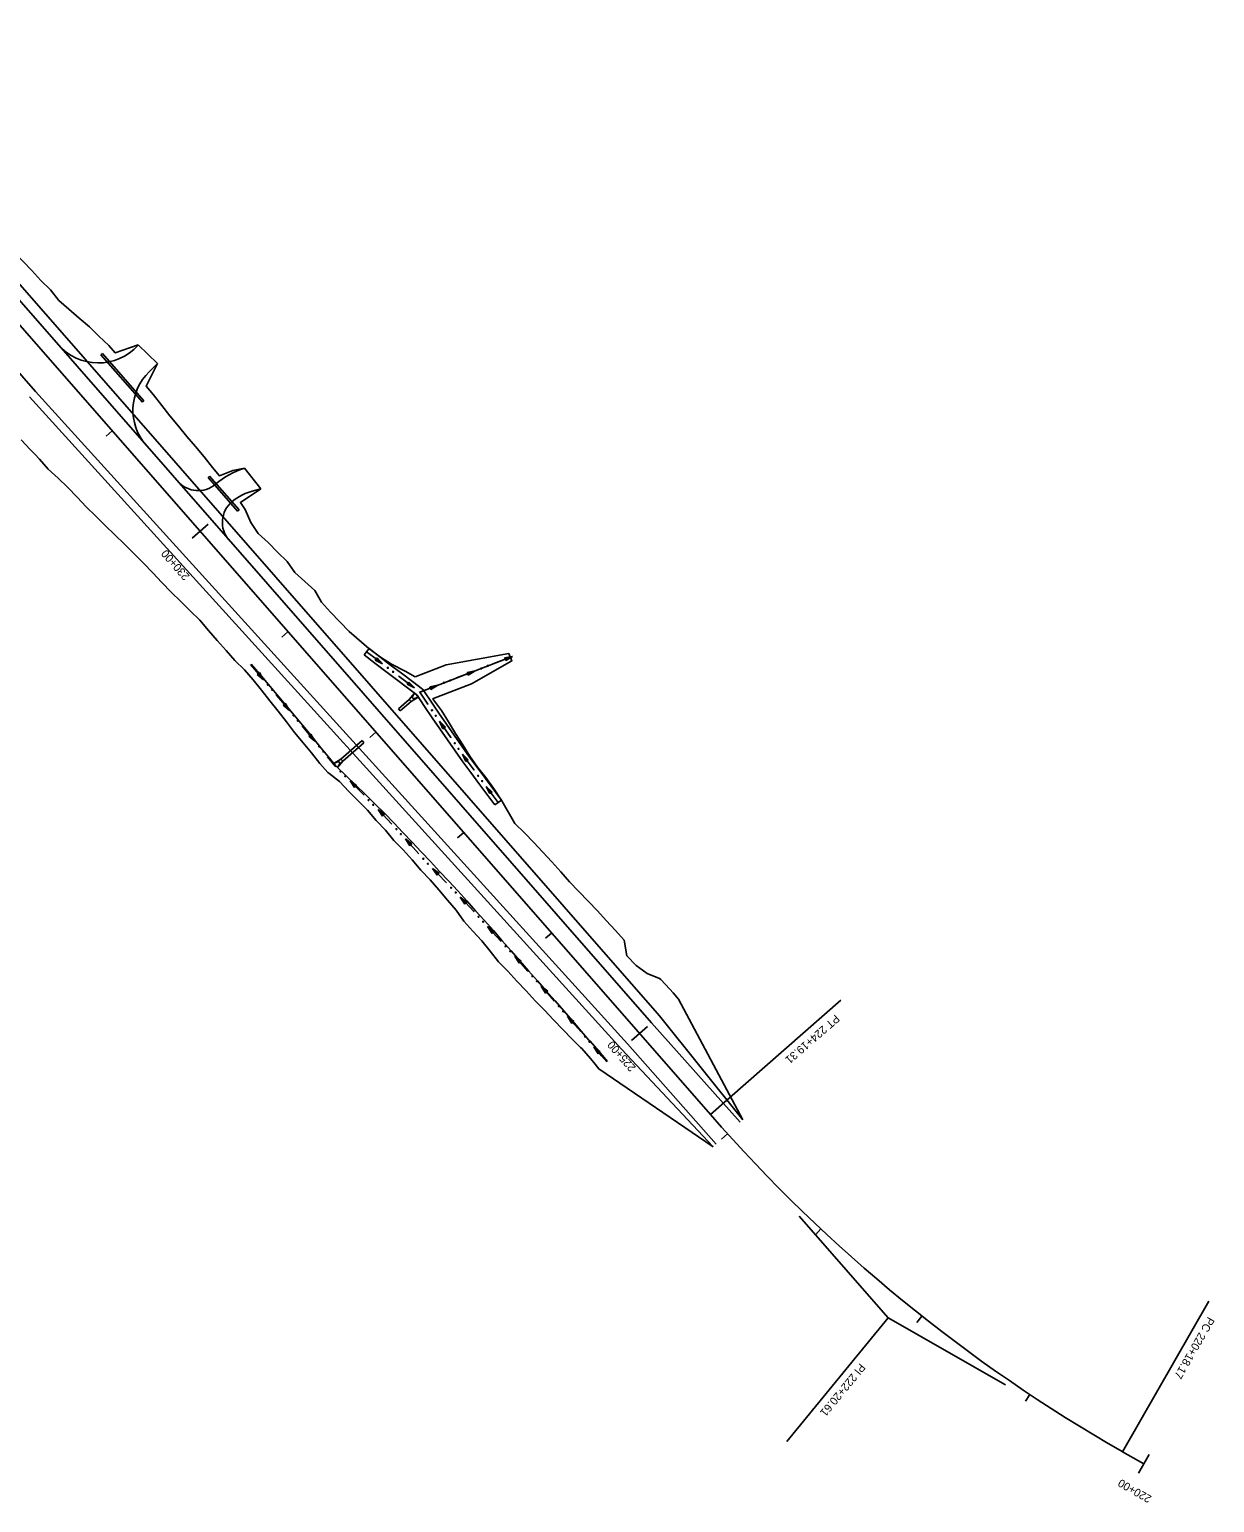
# Model space of a CAD drawing. Extents: x 948761 to 996004, y 1858548 to 1925175.
# Drawn here: x 966147 to 967035, y 1897160 to 1898265 of the extents above; entities that cross this region are included whole.
import ezdxf

# ---------------------------------------------------------------- set-up
doc = ezdxf.new("R2010")
doc.units = 0
for name, color, linetype in [('62', 7, 'Continuous'), ('R_Drainage', 7, 'Continuous'), ('R_Horz Alg', 7, 'Continuous'), ('R_Horz Alg Annot', 7, 'Continuous'), ('R_Proposed Const Limits', 7, 'Continuous'), ('R_Proposed Road', 7, 'Continuous')]:
    doc.layers.add(name, color=color, linetype=linetype)

msp = doc.modelspace()

# ---------------------------------------------------------------- linework, layer by layer
at = {"layer": '62'}
for p, q in [((966397.4, 1897795.9), (966401, 1897800.6)), ((966407, 1897793.6), (966405.7, 1897791.9)), ((966405.7, 1897791.9), (966411.1, 1897789.1)), ((966411.1, 1897789.1), (966407, 1897793.6)), ((966506.9, 1897794.1), (966438.6, 1897767.6)), ((966508.6, 1897794.7), (966502.6, 1897793.6)), ((966502.6, 1897793.6), (966503.4, 1897791.6)), ((966503.4, 1897791.6), (966508.6, 1897794.7)), ((966318.9, 1897782.5), (966317.3, 1897781.1)), ((966317.3, 1897781.1), (966322, 1897777.2)), ((966322, 1897777.2), (966318.9, 1897782.5)), ((966480.6, 1897783.9), (966474.6, 1897782.7)), ((966474.6, 1897782.7), (966475.4, 1897780.7)), ((966475.4, 1897780.7), (966480.6, 1897783.9)), ((966430.9, 1897775.4), (966429.6, 1897773.8)), ((966429.6, 1897773.8), (966435, 1897771)), ((966435, 1897771), (966430.9, 1897775.4)), ((966439.1, 1897767.8), (966452.6, 1897773)), ((966452.6, 1897773), (966446.6, 1897771.8)), ((966446.6, 1897771.8), (966447.4, 1897769.9)), ((966447.4, 1897769.9), (966452.6, 1897773)), ((966338.3, 1897759.5), (966336.6, 1897758.1)), ((966336.6, 1897758.1), (966341.3, 1897754.2)), ((966341.3, 1897754.2), (966338.3, 1897759.5)), ((966453.9, 1897746.1), (966456.4, 1897740.5)), ((966458.2, 1897741.7), (966453.9, 1897746.1)), ((966357.5, 1897736.4), (966355.8, 1897735)), ((966355.8, 1897735), (966360.4, 1897731.1)), ((966360.4, 1897731.1), (966357.5, 1897736.4)), ((966456.4, 1897740.5), (966458.2, 1897741.7)), ((966471, 1897721.4), (966473.6, 1897715.9)), ((966475.4, 1897717.1), (966471, 1897721.4)), ((966473.6, 1897715.9), (966475.4, 1897717.1)), ((966386.8, 1897701.3), (966390.2, 1897696.3)), ((966391.7, 1897697.8), (966386.8, 1897701.3)), ((966390.2, 1897696.3), (966391.7, 1897697.8)), ((966488.8, 1897697.2), (966491.5, 1897691.8)), ((966493.2, 1897693), (966488.8, 1897697.2)), ((966491.5, 1897691.8), (966493.2, 1897693)), ((966407.8, 1897679.8), (966411.2, 1897674.8)), ((966412.7, 1897676.3), (966407.8, 1897679.8)), ((966495.3, 1897683.4), (966500.2, 1897687)), ((966411.2, 1897674.8), (966412.7, 1897676.3)), ((966428.3, 1897657.9), (966431.5, 1897652.7)), ((966433.1, 1897654.1), (966428.3, 1897657.9)), ((966431.5, 1897652.7), (966433.1, 1897654.1)), ((966448.6, 1897635.8), (966452, 1897630.7)), ((966453.5, 1897632.2), (966448.6, 1897635.8)), ((966452, 1897630.7), (966453.5, 1897632.2)), ((966469.4, 1897614.1), (966472.8, 1897609)), ((966474.3, 1897610.5), (966469.4, 1897614.1)), ((966472.8, 1897609), (966474.3, 1897610.5)), ((966489.9, 1897592.1), (966493.2, 1897587)), ((966494.7, 1897588.4), (966489.9, 1897592.1)), ((966493.2, 1897587), (966494.7, 1897588.4)), ((966510.2, 1897570), (966513.4, 1897564.8)), ((966515, 1897566.2), (966510.2, 1897570)), ((966513.4, 1897564.8), (966515, 1897566.2)), ((966530.1, 1897547.5), (966533.3, 1897542.3)), ((966534.9, 1897543.7), (966530.1, 1897547.5)), ((966533.3, 1897542.3), (966534.9, 1897543.7)), ((966549.8, 1897524.9), (966553, 1897519.6)), ((966554.6, 1897521), (966549.8, 1897524.9)), ((966553, 1897519.6), (966554.6, 1897521)), ((966569.5, 1897502.1), (966572.6, 1897496.9)), ((966574.2, 1897498.3), (966569.5, 1897502.1)), ((966572.6, 1897496.9), (966574.2, 1897498.3))]:
    msp.add_line(p, q, dxfattribs=at)
for points in [[(966500.2, 1897687), (966488.2, 1897703.1), (966482.2, 1897711.1), (966476.3, 1897719.2), (966470.5, 1897727.3), (966464.8, 1897735.6), (966459, 1897743.9), (966453.3, 1897752.1), (966447.7, 1897760.4), (966442.1, 1897768.8), (966441.2, 1897770.1), (966433.5, 1897775.9), (966425.3, 1897782.1), (966417.2, 1897788.2), (966409.1, 1897794.4), (966401, 1897800.6)], [(966495.3, 1897683.4), (966483.4, 1897699.5), (966477.4, 1897707.6), (966471.4, 1897715.6), (966465.6, 1897723.9), (966459.8, 1897732.2), (966454.1, 1897740.4), (966448.4, 1897748.7), (966442.7, 1897757.1), (966437.1, 1897765.5), (966436.8, 1897765.9), (966429.9, 1897771.1), (966421.7, 1897777.3), (966413.6, 1897783.4), (966405.4, 1897789.6), (966397.4, 1897795.9)], [(966399.2, 1897798.2), (966407.3, 1897792), (966411.1, 1897789.1)], [(966494.6, 1897789.3), (966506.9, 1897794.1)], [(966312.2, 1897788.6), (966318.7, 1897781), (966322, 1897777.2)], [(966375.9, 1897712.8), (966370.2, 1897719.8), (966363.9, 1897727.5), (966357.6, 1897735.3), (966351.2, 1897743), (966344.8, 1897750.7), (966338.4, 1897758.4), (966332, 1897766.1), (966325.6, 1897773.7), (966319.1, 1897781.3), (966312.6, 1897788.9)], [(966423, 1897780), (966423.1, 1897780)], [(966423.1, 1897780), (966423.5, 1897779.7), (966431.7, 1897773.5), (966435, 1897771)], [(966466.6, 1897778.5), (966480.6, 1897783.9)], [(966466.6, 1897778.4), (966466.6, 1897778.5)], [(966494.6, 1897789.3), (966494.6, 1897789.3)], [(966445.4, 1897758.5), (966445.2, 1897758.8), (966439.6, 1897767.1), (966439, 1897768)], [(966331.7, 1897765.8), (966331.7, 1897765.8), (966331.7, 1897765.7)], [(966331.7, 1897765.7), (966338.1, 1897758.1), (966341.3, 1897754.2)], [(966445.4, 1897758.5), (966445.4, 1897758.5)], [(966462.4, 1897733.7), (966462.3, 1897733.9), (966456.6, 1897742.2), (966453.9, 1897746.1)], [(966350.9, 1897742.7), (966350.9, 1897742.6)], [(966350.9, 1897742.6), (966357.2, 1897735), (966360.4, 1897731.1)], [(966462.4, 1897733.7), (966462.4, 1897733.7)], [(966369.9, 1897719.4), (966375.6, 1897712.5)], [(966369.9, 1897719.4), (966369.9, 1897719.4)], [(966376.1, 1897711.9), (966375.6, 1897712.5)], [(966579.6, 1897491.1), (966575.7, 1897495.7), (966573.1, 1897498.7), (966566.6, 1897506.2), (966565.8, 1897507.1), (966560, 1897513.8), (966553.5, 1897521.4), (966547, 1897528.9), (966540.4, 1897536.5), (966533.8, 1897544), (966527.2, 1897551.5), (966520.6, 1897559), (966514, 1897566.5), (966507.5, 1897574.1), (966500.8, 1897581.6), (966494.2, 1897589.1), (966487.6, 1897596.6), (966480.9, 1897604), (966474.3, 1897611.5), (966467.5, 1897618.9), (966460.7, 1897626.2), (966453.9, 1897633.5), (966447.1, 1897640.9), (966440.2, 1897648.1), (966433.3, 1897655.4), (966426.4, 1897662.7), (966419.6, 1897669.9), (966412.5, 1897677.1), (966405.4, 1897684.1), (966398.3, 1897691.1), (966391.1, 1897698.2), (966383.9, 1897705.2), (966376.7, 1897712.1), (966375.9, 1897712.8)], [(966479.9, 1897709.3), (966479.8, 1897709.3), (966473.9, 1897717.4), (966471, 1897721.4)], [(966376.1, 1897711.9), (966376.1, 1897711.9)], [(966397.3, 1897690.6), (966390.4, 1897697.6), (966386.8, 1897701.3)], [(966479.9, 1897709.3), (966479.9, 1897709.3)], [(966397.3, 1897690.6), (966397.3, 1897690.6)], [(966497.7, 1897685.2), (966491.8, 1897693.2), (966488.8, 1897697.2)], [(966418.1, 1897669), (966411.4, 1897676.1), (966407.8, 1897679.8)], [(966418.2, 1897668.9), (966418.1, 1897669)], [(966438.4, 1897646.8), (966431.8, 1897654), (966428.3, 1897657.9)], [(966438.4, 1897646.8), (966438.4, 1897646.8)], [(966459, 1897625), (966452.2, 1897632), (966448.6, 1897635.8)], [(966459, 1897624.9), (966459, 1897625)], [(966479.7, 1897603.2), (966473, 1897610.4), (966469.4, 1897614.1)], [(966479.7, 1897603.2), (966479.7, 1897603.2)], [(966500.1, 1897581.1), (966493.4, 1897588.3), (966489.9, 1897592.1)], [(966500.1, 1897581.1), (966500.1, 1897581.1)], [(966520.1, 1897558.8), (966513.6, 1897566.2), (966510.2, 1897570)], [(966520.2, 1897558.7), (966520.1, 1897558.8)], [(966540, 1897536.2), (966533.5, 1897543.7), (966530.1, 1897547.5)], [(966540, 1897536.2), (966540, 1897536.2)], [(966559.6, 1897513.5), (966553.1, 1897521), (966549.8, 1897524.9)], [(966559.7, 1897513.5), (966559.7, 1897513.5), (966559.6, 1897513.5)], [(966579.3, 1897490.8), (966575.3, 1897495.4), (966572.7, 1897498.3), (966569.5, 1897502.1)]]:
    msp.add_lwpolyline(points, dxfattribs=at)
for centre in [(966415.1, 1897786.1), (966419.1, 1897783.1), (966485.2, 1897785.7), (966489.9, 1897787.5), (966325.2, 1897773.4), (966328.5, 1897769.6), (966457.2, 1897774.9), (966461.9, 1897776.7), (966344.5, 1897750.4), (966347.7, 1897746.5), (966448.2, 1897754.3), (966451, 1897750.2), (966363.6, 1897727.2), (966366.8, 1897723.3), (966465.2, 1897729.6), (966468.1, 1897725.4), (966379.7, 1897708.4), (966383.2, 1897704.8), (966482.8, 1897705.2), (966485.8, 1897701.2), (966400.7, 1897687), (966404.2, 1897683.4), (966421.5, 1897665.2), (966424.9, 1897661.5), (966441.7, 1897643), (966445.1, 1897639.3), (966462.5, 1897621.3), (966466, 1897617.7), (966483.1, 1897599.5), (966486.5, 1897595.8), (966503.4, 1897577.4), (966506.8, 1897573.7), (966523.4, 1897555), (966526.8, 1897551.2), (966543.3, 1897532.4), (966546.5, 1897528.6), (966562.9, 1897509.7), (966566.2, 1897505.9)]:
    msp.add_circle(centre, 0.375, dxfattribs=at)
at = {"layer": 'R_Drainage'}
for p, q in [((966201.2, 1898021.7), (966200.1, 1898020.7)), ((966232.3, 1897986.1), (966201.2, 1898021.7)), ((966200.1, 1898020.7), (966231.2, 1897985.1)), ((966231.2, 1897985.1), (966232.3, 1897986.1)), ((966281.6, 1897929.8), (966280.5, 1897928.8)), ((966280.5, 1897928.8), (966302.5, 1897903.5)), ((966303.7, 1897904.5), (966281.6, 1897929.8)), ((966302.5, 1897903.5), (966303.7, 1897904.5)), ((966431.2, 1897762.4), (966423.1, 1897755.4)), ((966432.5, 1897760.9), (966424.4, 1897753.9)), ((966431.2, 1897762.4), (966435.1, 1897767.2)), ((966432.5, 1897760.9), (966431.2, 1897762.4)), ((966432.5, 1897760.9), (966437.8, 1897764.2)), ((966435.1, 1897767.2), (966433.6, 1897764.7)), ((966437.8, 1897764.2), (966435.1, 1897767.2)), ((966437.8, 1897764.2), (966435.1, 1897763)), ((966395.9, 1897731.6), (966380, 1897717.7)), ((966397.2, 1897730), (966381.3, 1897716.2)), ((966380, 1897717.7), (966374.7, 1897714.4)), ((966374.7, 1897714.4), (966377.4, 1897715.6)), ((966374.7, 1897714.4), (966377.3, 1897711.4)), ((966381.3, 1897716.2), (966377.3, 1897711.4)), ((966377.3, 1897711.4), (966378.9, 1897713.9)), ((966380, 1897717.7), (966381.3, 1897716.2))]:
    msp.add_line(p, q, dxfattribs=at)
for points in [[(966423.1, 1897755.4), (966424.4, 1897753.9)], [(966397.2, 1897730), (966395.9, 1897731.6)]]:
    msp.add_lwpolyline(points, dxfattribs=at)
for centre, start, end in [((966434.6, 1897764.1), 148.6848, 293.625), ((966377.9, 1897714.5), 328.6848, 113.625)]:
    msp.add_arc(centre, 1.17, start, end, dxfattribs=at)
at = {"layer": 'R_Horz Alg'}
for p, q in [((966656.8, 1897451.3), (965957, 1898251.4)), ((966981.5, 1897189.4), (966965.7, 1897198.4)), ((966981.5, 1897189.4), (966965.7, 1897198.4))]:
    msp.add_line(p, q, dxfattribs=at)
msp.add_arc((967564.7, 1898245.4), 1206.2, 221.1731, 240.2272, dxfattribs=at)
at = {"layer": 'R_Horz Alg Annot'}
for p in [(966723.4, 1897375.1), (966877.9, 1897248.7)]:
    msp.add_line(p, (966790, 1897299), dxfattribs=at)
for points in [[(966204.1, 1897959.8), (966208.6, 1897963.7)], [(966268.4, 1897883.2), (966280.5, 1897893.7)], [(966335.8, 1897809.2), (966340.3, 1897813.2)], [(966401.6, 1897733.9), (966406.1, 1897737.9)], [(966467.4, 1897658.7), (966472, 1897662.6)], [(966533.3, 1897583.4), (966537.8, 1897587.3)], [(966656.8, 1897451.3), (966754.6, 1897536.9)], [(966597.6, 1897506.8), (966609.7, 1897517.3)], [(966665.1, 1897432.9), (966669.6, 1897436.9)], [(966735.5, 1897361.2), (966739.6, 1897365.6)], [(966965.7, 1897198.4), (967030.3, 1897311.3)], [(966790, 1897299), (966714, 1897206.1)], [(966811.6, 1897295.5), (966815.3, 1897300.2)], [(966892.8, 1897236.4), (966896.1, 1897241.4)], [(966977.5, 1897182.5), (966985.5, 1897196.4)]]:
    msp.add_lwpolyline(points, dxfattribs=at)
at = {"layer": 'R_Proposed Const Limits'}
for points in [[(966148.4, 1898083.8), (966141.5, 1898091), (966134.5, 1898098.2), (966127.6, 1898105.4), (966120.9, 1898112.8), (966114.6, 1898120.6), (966107, 1898127.3), (966101.4, 1898135.6), (966095.5, 1898143.7), (966089.6, 1898151.9), (966083.7, 1898160)], [(966228.1, 1898028.1), (966210.9, 1898022.1), (966206, 1898027.8), (966198.6, 1898034.7), (966191.6, 1898041.8), (966183.9, 1898048.3), (966176, 1898054.8), (966168.5, 1898061.5), (966162.4, 1898069.4), (966155.2, 1898076.4), (966148.4, 1898083.8)], [(966307.7, 1897935.7), (966298.9, 1897934), (966288.9, 1897930.1), (966283.7, 1897936.3), (966277.4, 1897944.2), (966271, 1897951.9), (966264.6, 1897959.5), (966258.2, 1897967.2), (966251.8, 1897974.9), (966245.7, 1897982.8), (966239.4, 1897990.6), (966234, 1897997.1), (966242.5, 1898014.2)], [(966307.7, 1897784.7), (966300.5, 1897791.6), (966293.9, 1897799.1), (966287.2, 1897806.6), (966280.8, 1897814.2), (966274.3, 1897821.9), (966267, 1897828.7), (966259.9, 1897835.9), (966252.8, 1897842.9), (966245.7, 1897850), (966238.9, 1897857.3), (966232, 1897864.6), (966224.9, 1897871.7), (966217.7, 1897878.7), (966210.6, 1897885.7), (966203.4, 1897892.7), (966196.2, 1897899.7), (966189.1, 1897906.8), (966182.2, 1897914), (966175.3, 1897921.3), (966168, 1897928.2), (966160.7, 1897935.1), (966154, 1897942.5), (966150.6, 1897946.2), (966147.1, 1897949.8), (966140.3, 1897957)], [(966312.4, 1897895), (966308.3, 1897904.7), (966304.6, 1897909.9), (966320, 1897920.2)], [(966400.9, 1897800.7), (966386.2, 1897813.4), (966379.2, 1897820.6), (966372.1, 1897827.7), (966365.5, 1897835.2), (966360.4, 1897844), (966352.8, 1897850.7), (966345.5, 1897857.5), (966339.8, 1897865.8), (966332.5, 1897872.7), (966325.5, 1897880), (966318, 1897886.7), (966312.4, 1897895)], [(966435.6, 1897779.3), (966428, 1897783.6), (966417.8, 1897788.9), (966409.5, 1897794.2), (966400.9, 1897800.7)], [(966505.8, 1897796.9), (966458.7, 1897788.3), (966435.6, 1897779.3)], [(966505.8, 1897796.9), (966508, 1897791.3), (966477.8, 1897774.2), (966448.5, 1897762.9)], [(966658.8, 1897427.2), (966573.2, 1897485.5), (966569.4, 1897490.2), (966567, 1897493.3), (966560.4, 1897500.8), (966559.5, 1897501.6), (966553.3, 1897507.9), (966546.3, 1897515.1), (966539.3, 1897522.2), (966532.4, 1897529.4), (966525.4, 1897536.6), (966518.7, 1897544), (966511.8, 1897551.3), (966505, 1897558.7), (966498, 1897565.8), (966491.9, 1897573.8), (966485.6, 1897581.6), (966478.7, 1897588.8), (966472.1, 1897596.3), (966466.2, 1897604.4), (966459.7, 1897612), (966453.4, 1897619.8), (966446.8, 1897627.3), (966439.8, 1897634.5), (966433.4, 1897642.1), (966426.7, 1897649.6), (966419.6, 1897656.7), (966413.3, 1897664.4), (966406.4, 1897671.7), (966399.9, 1897679.3), (966393, 1897686.5), (966385.8, 1897693.5), (966379, 1897700.9), (966370.9, 1897707.1), (966370.1, 1897707.7), (966364.1, 1897714.4), (966357.9, 1897722.3), (966351.6, 1897730), (966345.1, 1897737.7), (966339.1, 1897745.7), (966332.9, 1897753.5), (966326.7, 1897761.4), (966320.5, 1897769.3), (966314.2, 1897777), (966307.7, 1897784.7)], [(966500.5, 1897686.5), (966494.3, 1897695.8), (966488.5, 1897703.9), (966482.4, 1897711.7), (966476.6, 1897719.8), (966471.4, 1897728.5), (966465.9, 1897737), (966460.6, 1897745.6), (966455.2, 1897754.2), (966449.2, 1897762.2), (966448.5, 1897762.9)], [(966565.1, 1897611.2), (966558.1, 1897618.4), (966551.3, 1897625.8), (966544.7, 1897633.2), (966538, 1897640.7), (966531.3, 1897648), (966524.4, 1897655.3), (966517.4, 1897662.5), (966510.2, 1897669.5), (966500.5, 1897686.5)], [(966594.3, 1897570.3), (966592.3, 1897581.9), (966585.6, 1897589.3), (966578.7, 1897596.6), (966572.1, 1897604), (966565.1, 1897611.2)], [(966681.1, 1897447.3), (966633, 1897537.8), (966629, 1897542.4), (966626.4, 1897545.3), (966619.6, 1897552.6), (966618.6, 1897553.3), (966609.5, 1897557), (966601.1, 1897563), (966594.3, 1897570.3)]]:
    msp.add_lwpolyline(points, dxfattribs=at)
at = {"layer": 'R_Proposed Road'}
for p, q in [((966151.1, 1897993.1), (965938.9, 1898235.7)), ((966242.5, 1898014.2), (966228.1, 1898028.1)), ((966320, 1897920.2), (966307.7, 1897935.7)), ((966315.1, 1897919), (966320, 1897920.2)), ((966658.8, 1897427.2), (966590.1, 1897500.2)), ((966661.1, 1897429.2), (966661.1, 1897429.2))]:
    msp.add_line(p, q, dxfattribs=at)
for points in [[(966618.7, 1897525.2), (965972.1, 1898264.6)], [(966612.7, 1897520), (965966, 1898259.3)], [(966590.1, 1897500.2), (966146.6, 1897989.1)], [(966594.6, 1897504.2), (966151.1, 1897993.1)], [(966681.1, 1897447.3), (966618.7, 1897525.2)], [(966679.2, 1897445.6), (966612.7, 1897520)], [(966661.1, 1897429.2), (966594.6, 1897504.2)]]:
    msp.add_lwpolyline(points, dxfattribs=at)
for centre, radius, start, end in [((966198.2, 1898054.6), 40, 221.1731, 317.512), ((966143.6, 1898106.1), 115, 316.9537, 317.2708), ((966143.6, 1898106.1), 135, 313.52, 317.0683), ((966264.1, 1897979.2), 40, 133.52, 221.1731), ((966324.6, 1897879.1), 59, 106.6838, 130.8975), ((966272.9, 1897938.9), 20, 221.1731, 310.8975), ((966324.6, 1897879.1), 41, 103.4075, 130.1364), ((966311.1, 1897895.2), 20, 130.1364, 221.1731)]:
    msp.add_arc(centre, radius, start, end, dxfattribs=at)

# ---------------------------------------------------------------- texts
at = {"layer": 'R_Horz Alg'}
for rotation, p in [(131.1731, (966657.1, 1897451.7)), (131.1731, (966657.1, 1897451.7)), (150.2272, (966966, 1897198.9)), (150.2272, (966966, 1897198.9)), (150.2272, (966981.8, 1897189.8)), (150.2272, (966981.8, 1897189.8))]:
    msp.add_text('+', height=1, rotation=rotation, dxfattribs=at).set_placement(p)
at = {"layer": 'R_Horz Alg Annot'}
for s, rotation, p in [('230+00', 131.1731, (966267, 1897854.9)), ('PT 224+19.31', 221.1731, (966750.4, 1897526.6)), ('225+00', 131.1731, (966601.3, 1897486.7)), ('PC 220+18.17', 240.2272, (967029.7, 1897300.1)), ('PI 222+20.61', 230.7002, (966768.9, 1897265.2)), ('220+00', 150.2272, (966987.9, 1897165))]:
    msp.add_text(s, height=6, rotation=rotation, dxfattribs=at).set_placement(p)

doc.saveas('drawing.dxf')
